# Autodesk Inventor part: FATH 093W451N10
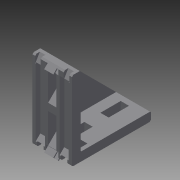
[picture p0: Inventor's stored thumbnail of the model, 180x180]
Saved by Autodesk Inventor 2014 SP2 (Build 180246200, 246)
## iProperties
Created: 2018-10
Part Number: FATH 093W451N10
Material: Generic
Catalog Web Link: www.cadenas.de
Description: Alu Connection Angle 45-Die-cast Aluminium, Profile 45 and up
Vendor: FATH
Document SubType Name: Modeling
Designer: psadmin
Manufacturer: FATH
Mass: 59.4439 g
Surface Area: 278.684 cm^2
Volume: 59.4439 cm^3
Density: 1 g/cm^3
Appearance: PSOLRGB-175-175-175
Category: PARTsolutions
Company: FATH
Title: FATH 093W451N10
Author: Cadenas PARTsolutions
Comments: Die-cast Aluminium, Profile 45 and up
PSOL_IDENT_0: {$CADENAS_DATA\23d-libs\fath\zubehoer_alu_sys\aluwinkel\093w451.prj},179 {VTYP=3D},{NB=FATH 093W451N
PSOL_IDENT_1: 10},{LINA=FATH 093W451N10},{NN=Alu Connection Angle 45},{DATE=19.02.2018 15:31:06},{GEOMDATE=21.03.2
PSOL_IDENT_2: 005},{VERSION=},{LINEID=740},{WBVAR=},{WBNUMERIC=}  {NB=FATH 093W451N10},{LINA=FATH 093W451N10},{KT=
PSOL_IDENT_3: DUMMY},{G=Aluwinkel 86x86x43},{N=10},{ARTNR=093W451N10},{PRTNO=},{NL=10},{NH=6.0},{NHA=5.4}
NN: Aluwinkel 45
NT: Aluminiumdruckguss, ab Profil 45
NB: FATH 093W451N10
NBSYN: FATH $ARTNR.
LINA: FATH 093W451N10
G: Aluwinkel 86x86x43
N: 10
ARTNR: 093W451N10
SUPPLIER: FATH
ARTICLENO: FATH 093W451N10
BOMINFO: FATH 093W451N10
CREATOR: CADENAS GmbH
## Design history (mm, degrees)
sketch "Skizze_1"
  geometry: L1 (8.5, 86)-(1.5, 86); L2 (1.5, 86)-(0, 84.5); L3 (0, 84.5)-(0, 1.5); L4 (1.5, 0)-(84.5, 0); L5 (84.5, 0)-(86, 1.5); L6 (86, 1.5)-(86, 8.5); L7 (86, 8.5)-(8.5, 86); A1 r 1.5 centre (1.5, 1.5) between (0, 1.5) and (1.5, 0)
  constraints: 14 end point, 2 point on circle, 1 centre point
extrude "Extrusion1" join sketch "Skizze_1" stored distance "d0" = 43; taper "d1" = 0 deg
sketch "Skizze_12"
  geometry: L1 (-86, 9.5)-(-10.5, 9.5); L2 (-9.5, 10.5)-(-9.5, 86); L3 (-9.5, 86)-(-86, 9.5); A1 r 1 centre (-10.5, 10.5) between (-10.5, 9.5) and (-9.5, 10.5)
  constraints: 6 end point, 2 point on circle, 1 centre point
extrude "Extrusion2" cut sketch "Skizze_12" distance "d2" = 37; taper "d3" = 0 deg
sketch "Skizze_3"
  geometry: L1 (-2, 79)-(-2, -2); L2 (-2, -2)-(79, -2); L3 (79, -2)-(79, 9.5); L4 (79, 9.5)-(56.876, 9.5); L5 (56.876, 9.5)-(46.376, -1); L6 (46.376, -1)-(39.5, -1); L7 (39.5, -1)-(39.5, 9.5); L8 (39.5, 9.5)-(16.571, 9.5); L9 (16.571, 9.5)-(6.071, -1); L10 (6.071, -1)-(-1, -1); L11 (-1, -1)-(-1, 6.071); L12 (-1, 6.071)-(9.5, 16.571); L13 (9.5, 16.571)-(9.5, 39.5); L14 (9.5, 39.5)-(-1, 39.5); L15 (-1, 39.5)-(-1, 46.376); L16 (-1, 46.376)-(9.5, 56.876); L17 (9.5, 56.876)-(9.5, 79); L18 (9.5, 79)-(-2, 79)
  constraints: 36 end point
extrude "Extrusion3" cut sketch "Skizze_3" stored distance "d4" = 9; taper "d5" = 0 deg
sketch "Skizze_4"
  geometry: L1 (0, 6.788)-(0, 0); L2 (0, 0)-(6.788, 0); L3 (6.788, 0)-(4.101, 2.687); L4 (4.101, 2.687)-(2.687, 1.273); L5 (2.687, 1.273)-(1.273, 2.687); L6 (1.273, 2.687)-(2.687, 4.101); L7 (2.687, 4.101)-(0, 6.788)
  constraints: 14 end point
extrude "Extrusion4" cut sketch "Skizze_4" stored distance "d6" = 13.5; taper "d7" = 0 deg
sketch "Skizze_5"
  geometry: L1 (0, 84.5)-(-4, 84.5); L2 (-4, 84.5)-(-4, -4); L3 (-4, -4)-(84.5, -4); L4 (84.5, -4)-(84.5, 0); L5 (84.5, 0)-(81.672, 2.828); L6 (81.672, 2.828)-(76.843, -2); L7 (76.843, -2)-(-2, -2); L8 (-2, -2)-(-2, 76.843); L9 (-2, 76.843)-(2.828, 81.672); L10 (2.828, 81.672)-(0, 84.5)
  constraints: 20 end point
extrude "Extrusion5" cut sketch "Skizze_5" stored distance "d8" = 13.5; taper "d9" = 0 deg
sketch "Skizze_6"
  geometry: L1 (1.131, 7.071)-(-3.818, 2.121); L2 (-3.818, 2.121)-(-2.97, 1.273); L3 (-2.97, 1.273)-(1.626, 5.869); L4 (1.626, 5.869)-(5.869, 1.626); L5 (5.869, 1.626)-(1.273, -2.97); L6 (1.273, -2.97)-(2.121, -3.818); L7 (2.121, -3.818)-(7.071, 1.131); L8 (7.071, 1.131)-(1.131, 7.071)
  constraints: 16 end point
extrude "Extrusion6" join sketch "Skizze_6" stored distance "d10" = 10; taper "d11" = 0 deg
sketch "Skizze_7"
  geometry: L1 (83.651, 0.849)-(79.833, -2.97); L2 (79.833, -2.97)-(80.682, -3.818); L3 (80.682, -3.818)-(84.5, 0); L4 (84.5, 0)-(83.651, 0.849)
  constraints: 8 end point
extrude "Extrusion7" join sketch "Skizze_7" stored distance "d12" = 10; taper "d13" = 0 deg
sketch "Skizze_8"
  geometry: L1 (0, 84.5)-(-3.818, 80.682); L2 (-3.818, 80.682)-(-2.97, 79.833); L3 (-2.97, 79.833)-(0.849, 83.651); L4 (0.849, 83.651)-(0, 84.5)
  constraints: 8 end point
extrude "Extrusion8" join sketch "Skizze_8" stored distance "d14" = 10; taper "d15" = 0 deg
sketch "Skizze_2"
  geometry: L1 (-20.814, 9.5)-(-9.5, 9.5); L2 (-9.5, 9.5)-(-9.5, 20.814); L3 (-9.5, 20.814)-(-20.814, 9.5)
  constraints: 6 end point
extrude "Extrusion9" join sketch "Skizze_2" stored distance "d16" = 4; taper "d17" = 0 deg
sketch "Skizze_9"
  geometry: L1 (-86, 5)-(-86, -2); L2 (-86, -2)-(2, -2); L3 (2, -2)-(2, 86); L4 (2, 86)-(-5, 86); L5 (-5, 86)-(1, 75.608); L6 (1, 75.608)-(1, -1); L7 (1, -1)-(-75.608, -1); L8 (-75.608, -1)-(-86, 5)
  constraints: 16 end point
extrude "Extrusion10" cut sketch "Skizze_9" stored distance "d18" = 6; taper "d19" = 0 deg
sketch "Skizze_14"
  geometry: L1 (-5.374, 0)-(0, 0); L2 (0, 0)-(0, 5.374); L3 (0, 5.374)-(-5.374, 0)
  constraints: 6 end point
extrude "Extrusion11" cut sketch "Skizze_14" stored distance "d20" = 7; taper "d21" = 0 deg
sketch "Skizze_11"
  geometry: L1 (-79, 0)-(-79, -4); L2 (-79, -4)-(4, -4); L3 (4, -4)-(4, 79); L4 (4, 79)-(0, 79); L5 (0, 79)-(-5, 74); L6 (-5, 74)-(-5, 9.243); L7 (-5, 9.243)-(2, 2.243); L8 (2, 2.243)-(2, -2); L9 (2, -2)-(-2.243, -2); L10 (-2.243, -2)-(-9.243, 5); L11 (-9.243, 5)-(-74, 5); L12 (-74, 5)-(-79, 0)
  constraints: 24 end point
extrude "Extrusion12" cut sketch "Skizze_11" stored distance "d22" = 10; taper "d23" = 0 deg
sketch "Skizze_15"
  geometry: L1 (-86, 5)-(-86, -2); L2 (-86, -2)-(2, -2); L3 (2, -2)-(2, 86); L4 (2, 86)-(-5, 86); L5 (-5, 86)-(1, 75.608); L6 (1, 75.608)-(1, -1); L7 (1, -1)-(-75.608, -1); L8 (-75.608, -1)-(-86, 5)
  constraints: 16 end point
extrude "Extrusion13" cut sketch "Skizze_15" stored distance "d24" = 6; taper "d25" = 0 deg
sketch "Skizze_10"
  geometry: L1 (-5.374, 0)-(0, 0); L2 (0, 0)-(0, 5.374); L3 (0, 5.374)-(-5.374, 0)
  constraints: 6 end point
extrude "Extrusion14" cut sketch "Skizze_10" stored distance "d26" = 7; taper "d27" = 0 deg
sketch "Skizze_13"
  geometry: L1 (-79, 0)-(-79, -4); L2 (-79, -4)-(4, -4); L3 (4, -4)-(4, 79); L4 (4, 79)-(0, 79); L5 (0, 79)-(-5, 74); L6 (-5, 74)-(-5, 9.243); L7 (-5, 9.243)-(2, 2.243); L8 (2, 2.243)-(2, -2); L9 (2, -2)-(-2.243, -2); L10 (-2.243, -2)-(-9.243, 5); L11 (-9.243, 5)-(-74, 5); L12 (-74, 5)-(-79, 0)
  constraints: 24 end point
extrude "Extrusion15" cut sketch "Skizze_13" stored distance "d28" = 10; taper "d29" = 0 deg
body "Solid1"
